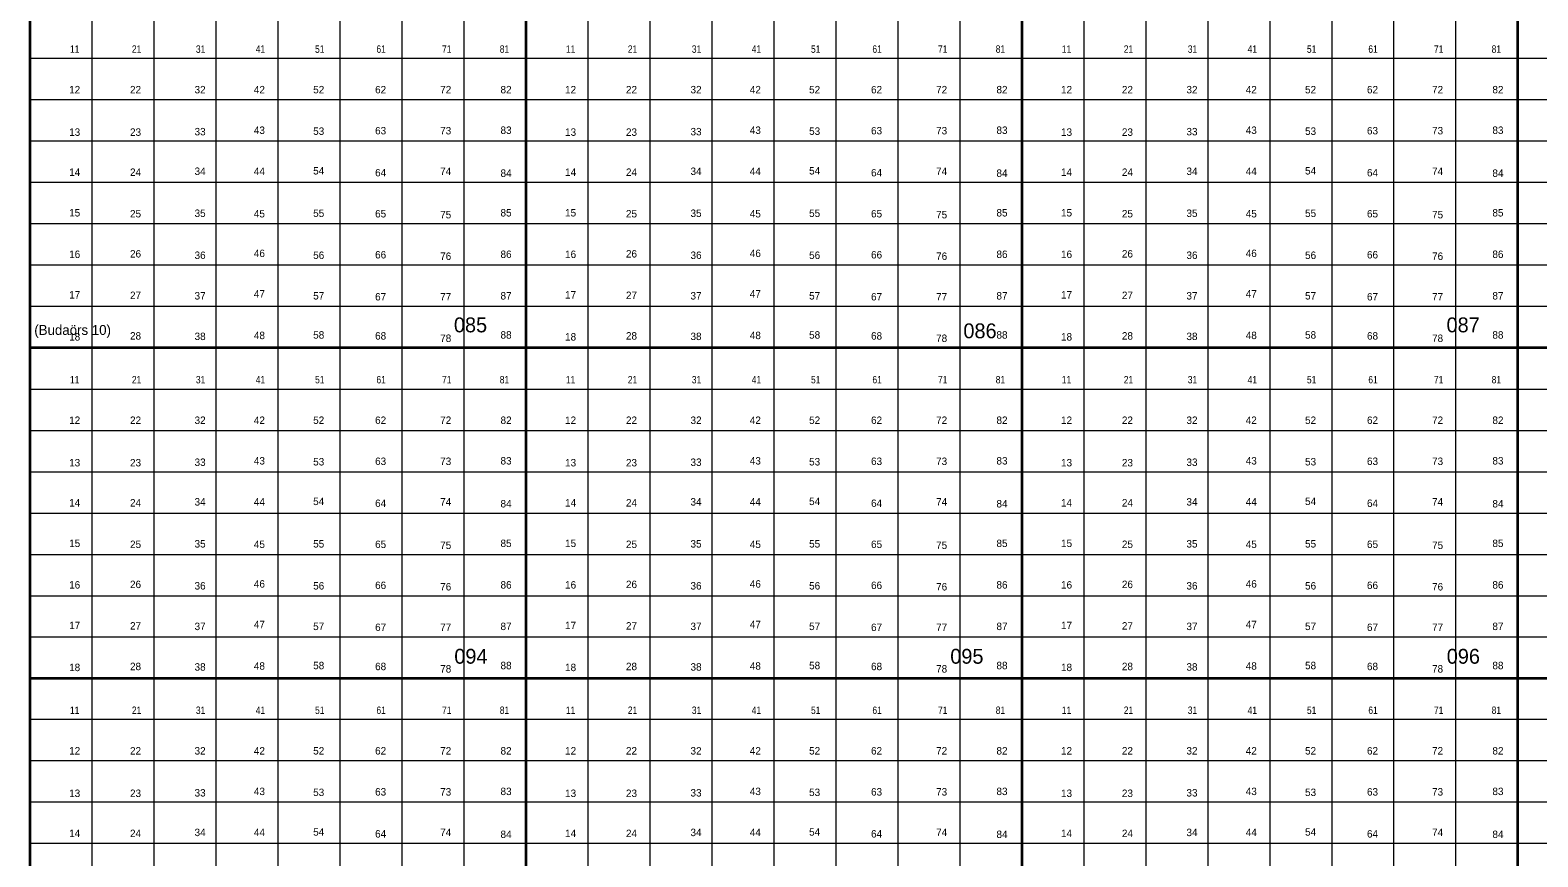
# Model space of a CAD drawing. Extents: x 639000 to 672000, y 222000 to 252000.
# Drawn here: x 642000 to 651120, y 228920 to 233921 of the extents above; entities that cross this region are included whole.
import ezdxf
from ezdxf.enums import TextEntityAlignment as Align

# ---------------------------------------------------------------- set-up
doc = ezdxf.new("R2010")
doc.units = 0
doc.header["$LTSCALE"] = 18
doc.layers.add('1', color=7, linetype='Continuous', lineweight=13)
doc.layers.add('2', color=7, linetype='Continuous')
doc.layers.add('29', color=7, linetype='Continuous')

msp = doc.modelspace()

# ---------------------------------------------------------------- linework, layer by layer
at = {"layer": '1', "lineweight": 35}
for p, q in [((648000, 224000), (648000, 252000)), ((651000, 224000), (651000, 252000)), ((645000, 224000), (645000, 250000)), ((642000, 224000), (642000, 248000)), ((669000, 232000), (642000, 232000)), ((642000, 230000), (669000, 230000))]:
    msp.add_line(p, q, dxfattribs=at)
at = {"layer": '1'}
for p, q in [((648375, 224000), (648375, 252000)), ((648750, 224000), (648750, 252000)), ((649125, 224000), (649125, 252000)), ((649500, 224000), (649500, 252000)), ((649875, 224000), (649875, 252000)), ((650250, 224000), (650250, 252000)), ((650625, 224000), (650625, 252000)), ((645375, 224000), (645375, 250000)), ((645750, 224000), (645750, 250000)), ((646125, 224000), (646125, 250000)), ((646500, 224000), (646500, 250000)), ((646875, 224000), (646875, 250000)), ((647250, 224000), (647250, 250000)), ((647625, 224000), (647625, 250000)), ((642375, 224000), (642375, 248000)), ((642750, 224000), (642750, 248000)), ((643125, 224000), (643125, 248000)), ((643500, 224000), (643500, 248000)), ((643875, 224000), (643875, 248000)), ((644250, 224000), (644250, 248000)), ((644625, 224000), (644625, 248000)), ((669000, 233750), (642000, 233750)), ((669000, 233500), (642000, 233500)), ((669000, 233250), (642000, 233250)), ((669000, 233000), (642000, 233000)), ((669000, 232750), (642000, 232750)), ((669000, 232500), (642000, 232500)), ((669000, 232250), (642000, 232250)), ((642000, 231750), (669000, 231750)), ((642000, 231500), (669000, 231500)), ((642000, 231250), (669000, 231250)), ((642000, 231000), (669000, 231000)), ((642000, 230750), (669000, 230750)), ((642000, 230500), (669000, 230500)), ((642000, 230250), (669000, 230250)), ((663000, 229750), (642000, 229750)), ((663000, 229500), (642000, 229500)), ((663000, 229250), (642000, 229250)), ((663000, 229000), (642000, 229000))]:
    msp.add_line(p, q, dxfattribs=at)

# ---------------------------------------------------------------- texts
at = {"layer": '2'}
msp.add_text('(Budaörs 10)', height=60, dxfattribs=at).set_placement((642256.94, 232077.5), align=Align.CENTER)
for s, p in [('085', (644663.68, 232093.25)), ('086', (647745.66, 232057.35)), ('087', (650668.28, 232093.25)), ('094', (644666.18, 230088.3)), ('095', (647666.28, 230088.3)), ('096', (650669.54, 230088.3))]:
    msp.add_text(s, height=90, rotation=359.94, dxfattribs=at).set_placement(p, align=Align.CENTER)
at = {"layer": '29', "width": 0.85}
for s, p in [('11', (642269.26, 233784.35)), ('21', (642643.86, 233784.35)), ('31', (643031.16, 233784.35)), ('41', (643393.07, 233784.35)), ('51', (643751.8, 233784.35)), ('61', (644123.23, 233784.35)), ('71', (644520.05, 233784.35)), ('81', (644869.26, 233784.35)), ('11', (645269.26, 233784.35)), ('21', (645643.86, 233784.35)), ('31', (646031.16, 233784.35)), ('41', (646393.07, 233784.35)), ('51', (646751.8, 233784.35)), ('61', (647123.23, 233784.35)), ('71', (647520.05, 233784.35)), ('81', (647869.26, 233784.35)), ('11', (648269.26, 233784.35)), ('21', (648643.86, 233784.35)), ('31', (649031.16, 233784.35)), ('41', (649393.07, 233784.35)), ('51', (649751.8, 233784.35)), ('61', (650123.23, 233784.35)), ('71', (650520.05, 233784.35)), ('81', (650869.26, 233784.35)), ('11', (642269.26, 231784.35)), ('21', (642643.86, 231784.35)), ('31', (643031.16, 231784.35)), ('41', (643393.07, 231784.35)), ('51', (643751.8, 231784.35)), ('61', (644123.23, 231784.35)), ('71', (644520.05, 231784.35)), ('81', (644869.26, 231784.35)), ('11', (645269.26, 231784.35)), ('21', (645643.86, 231784.35)), ('31', (646031.16, 231784.35)), ('41', (646393.07, 231784.35)), ('51', (646751.8, 231784.35)), ('61', (647123.23, 231784.35)), ('71', (647520.05, 231784.35)), ('81', (647869.26, 231784.35)), ('11', (648269.26, 231784.35)), ('21', (648643.86, 231784.35)), ('31', (649031.16, 231784.35)), ('41', (649393.07, 231784.35)), ('51', (649751.8, 231784.35)), ('61', (650123.23, 231784.35)), ('71', (650520.05, 231784.35)), ('81', (650869.26, 231784.35)), ('11', (642269.26, 229784.35)), ('21', (642643.86, 229784.35)), ('31', (643031.16, 229784.35)), ('41', (643393.07, 229784.35)), ('51', (643751.8, 229784.35)), ('61', (644123.23, 229784.35)), ('71', (644520.05, 229784.35)), ('81', (644869.26, 229784.35)), ('11', (645269.26, 229784.35)), ('21', (645643.86, 229784.35)), ('31', (646031.16, 229784.35)), ('41', (646393.07, 229784.35)), ('51', (646751.8, 229784.35)), ('61', (647123.23, 229784.35)), ('71', (647520.05, 229784.35)), ('81', (647869.26, 229784.35)), ('11', (648269.26, 229784.35)), ('21', (648643.86, 229784.35)), ('31', (649031.16, 229784.35)), ('41', (649393.07, 229784.35)), ('51', (649751.8, 229784.35)), ('61', (650123.23, 229784.35)), ('71', (650520.05, 229784.35)), ('81', (650869.26, 229784.35))]:
    msp.add_text(s, height=45, dxfattribs=at).set_placement(p, align=Align.CENTER)
at = {"layer": '29'}
for s, p in [('12', (642269.25, 233538.96)), ('22', (642637.51, 233538.96)), ('32', (643027.99, 233538.96)), ('42', (643386.72, 233538.96)), ('52', (643745.45, 233538.96)), ('62', (644120.05, 233538.96)), ('72', (644513.7, 233538.96)), ('82', (644878.78, 233538.96)), ('12', (645269.25, 233538.96)), ('22', (645637.51, 233538.96)), ('32', (646027.99, 233538.96)), ('42', (646386.72, 233538.96)), ('52', (646745.45, 233538.96)), ('62', (647120.05, 233538.96)), ('72', (647513.7, 233538.96)), ('82', (647878.78, 233538.96)), ('12', (648269.25, 233538.96)), ('22', (648637.51, 233538.96)), ('32', (649027.99, 233538.96)), ('42', (649386.72, 233538.96)), ('52', (649745.45, 233538.96)), ('62', (650120.05, 233538.96)), ('72', (650513.7, 233538.96)), ('82', (650878.78, 233538.96)), ('13', (642269.26, 233282.02)), ('23', (642637.51, 233282.02)), ('33', (643027.99, 233284.91)), ('43', (643386.72, 233293.57)), ('53', (643745.45, 233287.8)), ('63', (644120.05, 233290.68)), ('73', (644513.7, 233290.68)), ('83', (644878.78, 233293.57)), ('13', (645269.26, 233282.02)), ('23', (645637.51, 233282.02)), ('33', (646027.99, 233284.91)), ('43', (646386.72, 233293.57)), ('53', (646745.45, 233287.8)), ('63', (647120.05, 233290.68)), ('73', (647513.7, 233290.68)), ('83', (647878.78, 233293.57)), ('13', (648269.26, 233282.02)), ('23', (648637.51, 233282.02)), ('33', (649027.99, 233284.91)), ('43', (649386.72, 233293.57)), ('53', (649745.45, 233287.8)), ('63', (650120.05, 233290.68)), ('73', (650513.7, 233290.68)), ('83', (650878.78, 233293.57)), ('14', (642269.26, 233039.52)), ('24', (642637.51, 233039.52)), ('34', (643027.99, 233045.29)), ('44', (643386.72, 233045.29)), ('54', (643745.45, 233048.18)), ('64', (644120.05, 233036.63)), ('74', (644513.7, 233045.29)), ('84', (644878.78, 233033.74)), ('14', (645269.26, 233039.52)), ('24', (645637.51, 233039.52)), ('34', (646027.99, 233045.29)), ('44', (646386.72, 233045.29)), ('54', (646745.45, 233048.18)), ('64', (647120.05, 233036.63)), ('74', (647513.7, 233045.29)), ('84', (647878.78, 233033.74)), ('14', (648269.26, 233039.52)), ('24', (648637.51, 233039.52)), ('34', (649027.99, 233045.29)), ('44', (649386.72, 233045.29)), ('54', (649745.45, 233048.18)), ('64', (650120.05, 233036.63)), ('74', (650513.7, 233045.29)), ('84', (650878.78, 233033.74)), ('15', (642269.26, 232794.13)), ('85', (644878.78, 232794.13)), ('15', (645269.26, 232794.13)), ('85', (647878.78, 232794.13)), ('15', (648269.26, 232794.13)), ('85', (650878.78, 232794.13)), ('25', (642637.51, 232788.35)), ('35', (643027.99, 232791.24)), ('45', (643386.72, 232788.35)), ('55', (643745.45, 232791.24)), ('65', (644120.05, 232788.36)), ('75', (644513.7, 232782.58)), ('25', (645637.51, 232788.35)), ('35', (646027.99, 232791.24)), ('45', (646386.72, 232788.35)), ('55', (646745.45, 232791.24)), ('65', (647120.05, 232788.36)), ('75', (647513.7, 232782.58)), ('25', (648637.51, 232788.35)), ('35', (649027.99, 232791.24)), ('45', (649386.72, 232788.35)), ('55', (649745.45, 232791.24)), ('65', (650120.05, 232788.36)), ('75', (650513.7, 232782.58)), ('16', (642269.26, 232542.96)), ('26', (642637.51, 232545.85)), ('36', (643027.99, 232537.19)), ('46', (643386.72, 232548.74)), ('56', (643745.45, 232537.19)), ('66', (644120.05, 232540.08)), ('76', (644513.7, 232531.42)), ('86', (644878.78, 232542.96)), ('16', (645269.26, 232542.96)), ('26', (645637.51, 232545.85)), ('36', (646027.99, 232537.19)), ('46', (646386.72, 232548.74)), ('56', (646745.45, 232537.19)), ('66', (647120.05, 232540.08)), ('76', (647513.7, 232531.42)), ('86', (647878.78, 232542.96)), ('16', (648269.26, 232542.96)), ('26', (648637.51, 232545.85)), ('36', (649027.99, 232537.19)), ('46', (649386.72, 232548.74)), ('56', (649745.45, 232537.19)), ('66', (650120.05, 232540.08)), ('76', (650513.7, 232531.42)), ('86', (650878.78, 232542.96)), ('17', (642269.26, 232297.57)), ('27', (642637.51, 232294.69)), ('37', (643027.99, 232291.8)), ('47', (643386.72, 232303.35)), ('57', (643745.45, 232291.8)), ('67', (644120.05, 232286.03)), ('77', (644513.7, 232286.03)), ('87', (644878.78, 232291.8)), ('17', (645269.26, 232297.57)), ('27', (645637.51, 232294.69)), ('37', (646027.99, 232291.8)), ('47', (646386.72, 232303.35)), ('57', (646745.45, 232291.8)), ('67', (647120.05, 232286.03)), ('77', (647513.7, 232286.03)), ('87', (647878.78, 232291.8)), ('17', (648269.26, 232297.57)), ('27', (648637.51, 232294.69)), ('37', (649027.99, 232291.8)), ('47', (649386.72, 232303.35)), ('57', (649745.45, 232291.8)), ('67', (650120.05, 232286.03)), ('77', (650513.7, 232286.03)), ('87', (650878.78, 232291.8)), ('18', (642269.25, 232043.52)), ('28', (642637.51, 232049.3)), ('38', (643027.99, 232046.41)), ('48', (643386.72, 232052.18)), ('58', (643745.45, 232055.07)), ('68', (644120.05, 232049.3)), ('78', (644513.7, 232034.86)), ('88', (644878.78, 232055.07)), ('18', (645269.25, 232043.52)), ('28', (645637.51, 232049.3)), ('38', (646027.99, 232046.41)), ('48', (646386.72, 232052.18)), ('58', (646745.45, 232055.07)), ('68', (647120.05, 232049.3)), ('78', (647513.7, 232034.86)), ('88', (647878.78, 232055.07)), ('18', (648269.25, 232043.52)), ('28', (648637.51, 232049.3)), ('38', (649027.99, 232046.41)), ('48', (649386.72, 232052.18)), ('58', (649745.45, 232055.07)), ('68', (650120.05, 232049.3)), ('78', (650513.7, 232034.86)), ('88', (650878.78, 232055.07)), ('12', (642269.25, 231538.96)), ('22', (642637.51, 231538.96)), ('32', (643027.99, 231538.96)), ('42', (643386.72, 231538.96)), ('52', (643745.45, 231538.96)), ('62', (644120.05, 231538.96)), ('72', (644513.7, 231538.96)), ('82', (644878.78, 231538.96)), ('12', (645269.25, 231538.96)), ('22', (645637.51, 231538.96)), ('32', (646027.99, 231538.96)), ('42', (646386.72, 231538.96)), ('52', (646745.45, 231538.96)), ('62', (647120.05, 231538.96)), ('72', (647513.7, 231538.96)), ('82', (647878.78, 231538.96)), ('12', (648269.25, 231538.96)), ('22', (648637.51, 231538.96)), ('32', (649027.99, 231538.96)), ('42', (649386.72, 231538.96)), ('52', (649745.45, 231538.96)), ('62', (650120.05, 231538.96)), ('72', (650513.7, 231538.96)), ('82', (650878.78, 231538.96)), ('13', (642269.26, 231282.02)), ('23', (642637.51, 231282.02)), ('33', (643027.99, 231284.91)), ('43', (643386.72, 231293.57)), ('53', (643745.45, 231287.8)), ('63', (644120.05, 231290.68)), ('73', (644513.7, 231290.68)), ('83', (644878.78, 231293.57)), ('13', (645269.26, 231282.02)), ('23', (645637.51, 231282.02)), ('33', (646027.99, 231284.91)), ('43', (646386.72, 231293.57)), ('53', (646745.45, 231287.8)), ('63', (647120.05, 231290.68)), ('73', (647513.7, 231290.68)), ('83', (647878.78, 231293.57)), ('13', (648269.26, 231282.02)), ('23', (648637.51, 231282.02)), ('33', (649027.99, 231284.91)), ('43', (649386.72, 231293.57)), ('53', (649745.45, 231287.8)), ('63', (650120.05, 231290.68)), ('73', (650513.7, 231290.68)), ('83', (650878.78, 231293.57)), ('14', (642269.26, 231039.52)), ('24', (642637.51, 231039.52)), ('34', (643027.99, 231045.29)), ('44', (643386.72, 231045.29)), ('54', (643745.45, 231048.18)), ('64', (644120.05, 231036.63)), ('74', (644513.7, 231045.29)), ('84', (644878.78, 231033.74)), ('14', (645269.26, 231039.52)), ('24', (645637.51, 231039.52)), ('34', (646027.99, 231045.29)), ('44', (646386.72, 231045.29)), ('54', (646745.45, 231048.18)), ('64', (647120.05, 231036.63)), ('74', (647513.7, 231045.29)), ('84', (647878.78, 231033.74)), ('14', (648269.26, 231039.52)), ('24', (648637.51, 231039.52)), ('34', (649027.99, 231045.29)), ('44', (649386.72, 231045.29)), ('54', (649745.45, 231048.18)), ('64', (650120.05, 231036.63)), ('74', (650513.7, 231045.29)), ('84', (650878.78, 231033.74)), ('15', (642269.26, 230794.13)), ('25', (642637.51, 230788.35)), ('35', (643027.99, 230791.24)), ('45', (643386.72, 230788.35)), ('55', (643745.45, 230791.24)), ('65', (644120.05, 230788.36)), ('85', (644878.78, 230794.13)), ('15', (645269.26, 230794.13)), ('25', (645637.51, 230788.35)), ('35', (646027.99, 230791.24)), ('45', (646386.72, 230788.35)), ('55', (646745.45, 230791.24)), ('65', (647120.05, 230788.36)), ('85', (647878.78, 230794.13)), ('15', (648269.26, 230794.13)), ('25', (648637.51, 230788.35)), ('35', (649027.99, 230791.24)), ('45', (649386.72, 230788.35)), ('55', (649745.45, 230791.24)), ('65', (650120.05, 230788.36)), ('85', (650878.78, 230794.13)), ('75', (644513.7, 230782.58)), ('75', (647513.7, 230782.58)), ('75', (650513.7, 230782.58)), ('16', (642269.26, 230542.96)), ('26', (642637.51, 230545.85)), ('36', (643027.99, 230537.19)), ('46', (643386.72, 230548.74)), ('56', (643745.45, 230537.19)), ('66', (644120.05, 230540.08)), ('76', (644513.7, 230531.42)), ('86', (644878.78, 230542.96)), ('16', (645269.26, 230542.96)), ('26', (645637.51, 230545.85)), ('36', (646027.99, 230537.19)), ('46', (646386.72, 230548.74)), ('56', (646745.45, 230537.19)), ('66', (647120.05, 230540.08)), ('76', (647513.7, 230531.42)), ('86', (647878.78, 230542.96)), ('16', (648269.26, 230542.96)), ('26', (648637.51, 230545.85)), ('36', (649027.99, 230537.19)), ('46', (649386.72, 230548.74)), ('56', (649745.45, 230537.19)), ('66', (650120.05, 230540.08)), ('76', (650513.7, 230531.42)), ('86', (650878.78, 230542.96)), ('17', (642269.26, 230297.57)), ('27', (642637.51, 230294.69)), ('37', (643027.99, 230291.8)), ('47', (643386.72, 230303.35)), ('57', (643745.45, 230291.8)), ('67', (644120.05, 230286.03)), ('77', (644513.7, 230286.03)), ('87', (644878.78, 230291.8)), ('17', (645269.26, 230297.57)), ('27', (645637.51, 230294.69)), ('37', (646027.99, 230291.8)), ('47', (646386.72, 230303.35)), ('57', (646745.45, 230291.8)), ('67', (647120.05, 230286.03)), ('77', (647513.7, 230286.03)), ('87', (647878.78, 230291.8)), ('17', (648269.26, 230297.57)), ('27', (648637.51, 230294.69)), ('37', (649027.99, 230291.8)), ('47', (649386.72, 230303.35)), ('57', (649745.45, 230291.8)), ('67', (650120.05, 230286.03)), ('77', (650513.7, 230286.03)), ('87', (650878.78, 230291.8)), ('18', (642269.25, 230043.52)), ('28', (642637.51, 230049.3)), ('38', (643027.99, 230046.41)), ('48', (643386.72, 230052.18)), ('58', (643745.45, 230055.07)), ('68', (644120.05, 230049.3)), ('78', (644513.7, 230034.86)), ('88', (644878.78, 230055.07)), ('18', (645269.25, 230043.52)), ('28', (645637.51, 230049.3)), ('38', (646027.99, 230046.41)), ('48', (646386.72, 230052.18)), ('58', (646745.45, 230055.07)), ('68', (647120.05, 230049.3)), ('78', (647513.7, 230034.86)), ('88', (647878.78, 230055.07)), ('18', (648269.25, 230043.52)), ('28', (648637.51, 230049.3)), ('38', (649027.99, 230046.41)), ('48', (649386.72, 230052.18)), ('58', (649745.45, 230055.07)), ('68', (650120.05, 230049.3)), ('78', (650513.7, 230034.86)), ('88', (650878.78, 230055.07)), ('12', (642269.25, 229538.96)), ('22', (642637.51, 229538.96)), ('32', (643027.99, 229538.96)), ('42', (643386.72, 229538.96)), ('52', (643745.45, 229538.96)), ('62', (644120.05, 229538.96)), ('72', (644513.7, 229538.96)), ('82', (644878.78, 229538.96)), ('12', (645269.25, 229538.96)), ('22', (645637.51, 229538.96)), ('32', (646027.99, 229538.96)), ('42', (646386.72, 229538.96)), ('52', (646745.45, 229538.96)), ('62', (647120.05, 229538.96)), ('72', (647513.7, 229538.96)), ('82', (647878.78, 229538.96)), ('12', (648269.25, 229538.96)), ('22', (648637.51, 229538.96)), ('32', (649027.99, 229538.96)), ('42', (649386.72, 229538.96)), ('52', (649745.45, 229538.96)), ('62', (650120.05, 229538.96)), ('72', (650513.7, 229538.96)), ('82', (650878.78, 229538.96)), ('13', (642269.26, 229282.02)), ('23', (642637.51, 229282.02)), ('33', (643027.99, 229284.91)), ('43', (643386.72, 229293.57)), ('53', (643745.45, 229287.8)), ('63', (644120.05, 229290.68)), ('73', (644513.7, 229290.68)), ('83', (644878.78, 229293.57)), ('13', (645269.26, 229282.02)), ('23', (645637.51, 229282.02)), ('33', (646027.99, 229284.91)), ('43', (646386.72, 229293.57)), ('53', (646745.45, 229287.8)), ('63', (647120.05, 229290.68)), ('73', (647513.7, 229290.68)), ('83', (647878.78, 229293.57)), ('13', (648269.26, 229282.02)), ('23', (648637.51, 229282.02)), ('33', (649027.99, 229284.91)), ('43', (649386.72, 229293.57)), ('53', (649745.45, 229287.8)), ('63', (650120.05, 229290.68)), ('73', (650513.7, 229290.68)), ('83', (650878.78, 229293.57)), ('14', (642269.26, 229039.52)), ('24', (642637.51, 229039.52)), ('34', (643027.99, 229045.29)), ('44', (643386.72, 229045.29)), ('54', (643745.45, 229048.18)), ('64', (644120.05, 229036.63)), ('74', (644513.7, 229045.29)), ('84', (644878.78, 229033.74)), ('14', (645269.26, 229039.52)), ('24', (645637.51, 229039.52)), ('34', (646027.99, 229045.29)), ('44', (646386.72, 229045.29)), ('54', (646745.45, 229048.18)), ('64', (647120.05, 229036.63)), ('74', (647513.7, 229045.29)), ('84', (647878.78, 229033.74)), ('14', (648269.26, 229039.52)), ('24', (648637.51, 229039.52)), ('34', (649027.99, 229045.29)), ('44', (649386.72, 229045.29)), ('54', (649745.45, 229048.18)), ('64', (650120.05, 229036.63)), ('74', (650513.7, 229045.29)), ('84', (650878.78, 229033.74))]:
    msp.add_text(s, height=45, dxfattribs=at).set_placement(p, align=Align.CENTER)

doc.saveas('drawing.dxf')
